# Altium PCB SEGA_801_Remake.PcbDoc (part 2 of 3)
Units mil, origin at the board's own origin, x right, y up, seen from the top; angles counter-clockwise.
Board outline 5905.51 x 7590.41 mil, 2 copper layers (Top Layer, Bottom Layer), stack 61.811 mil thick; 192 components, 203 nets, 858 pads, 614 vias.
Unrouted connection lines stored in the file: 107.
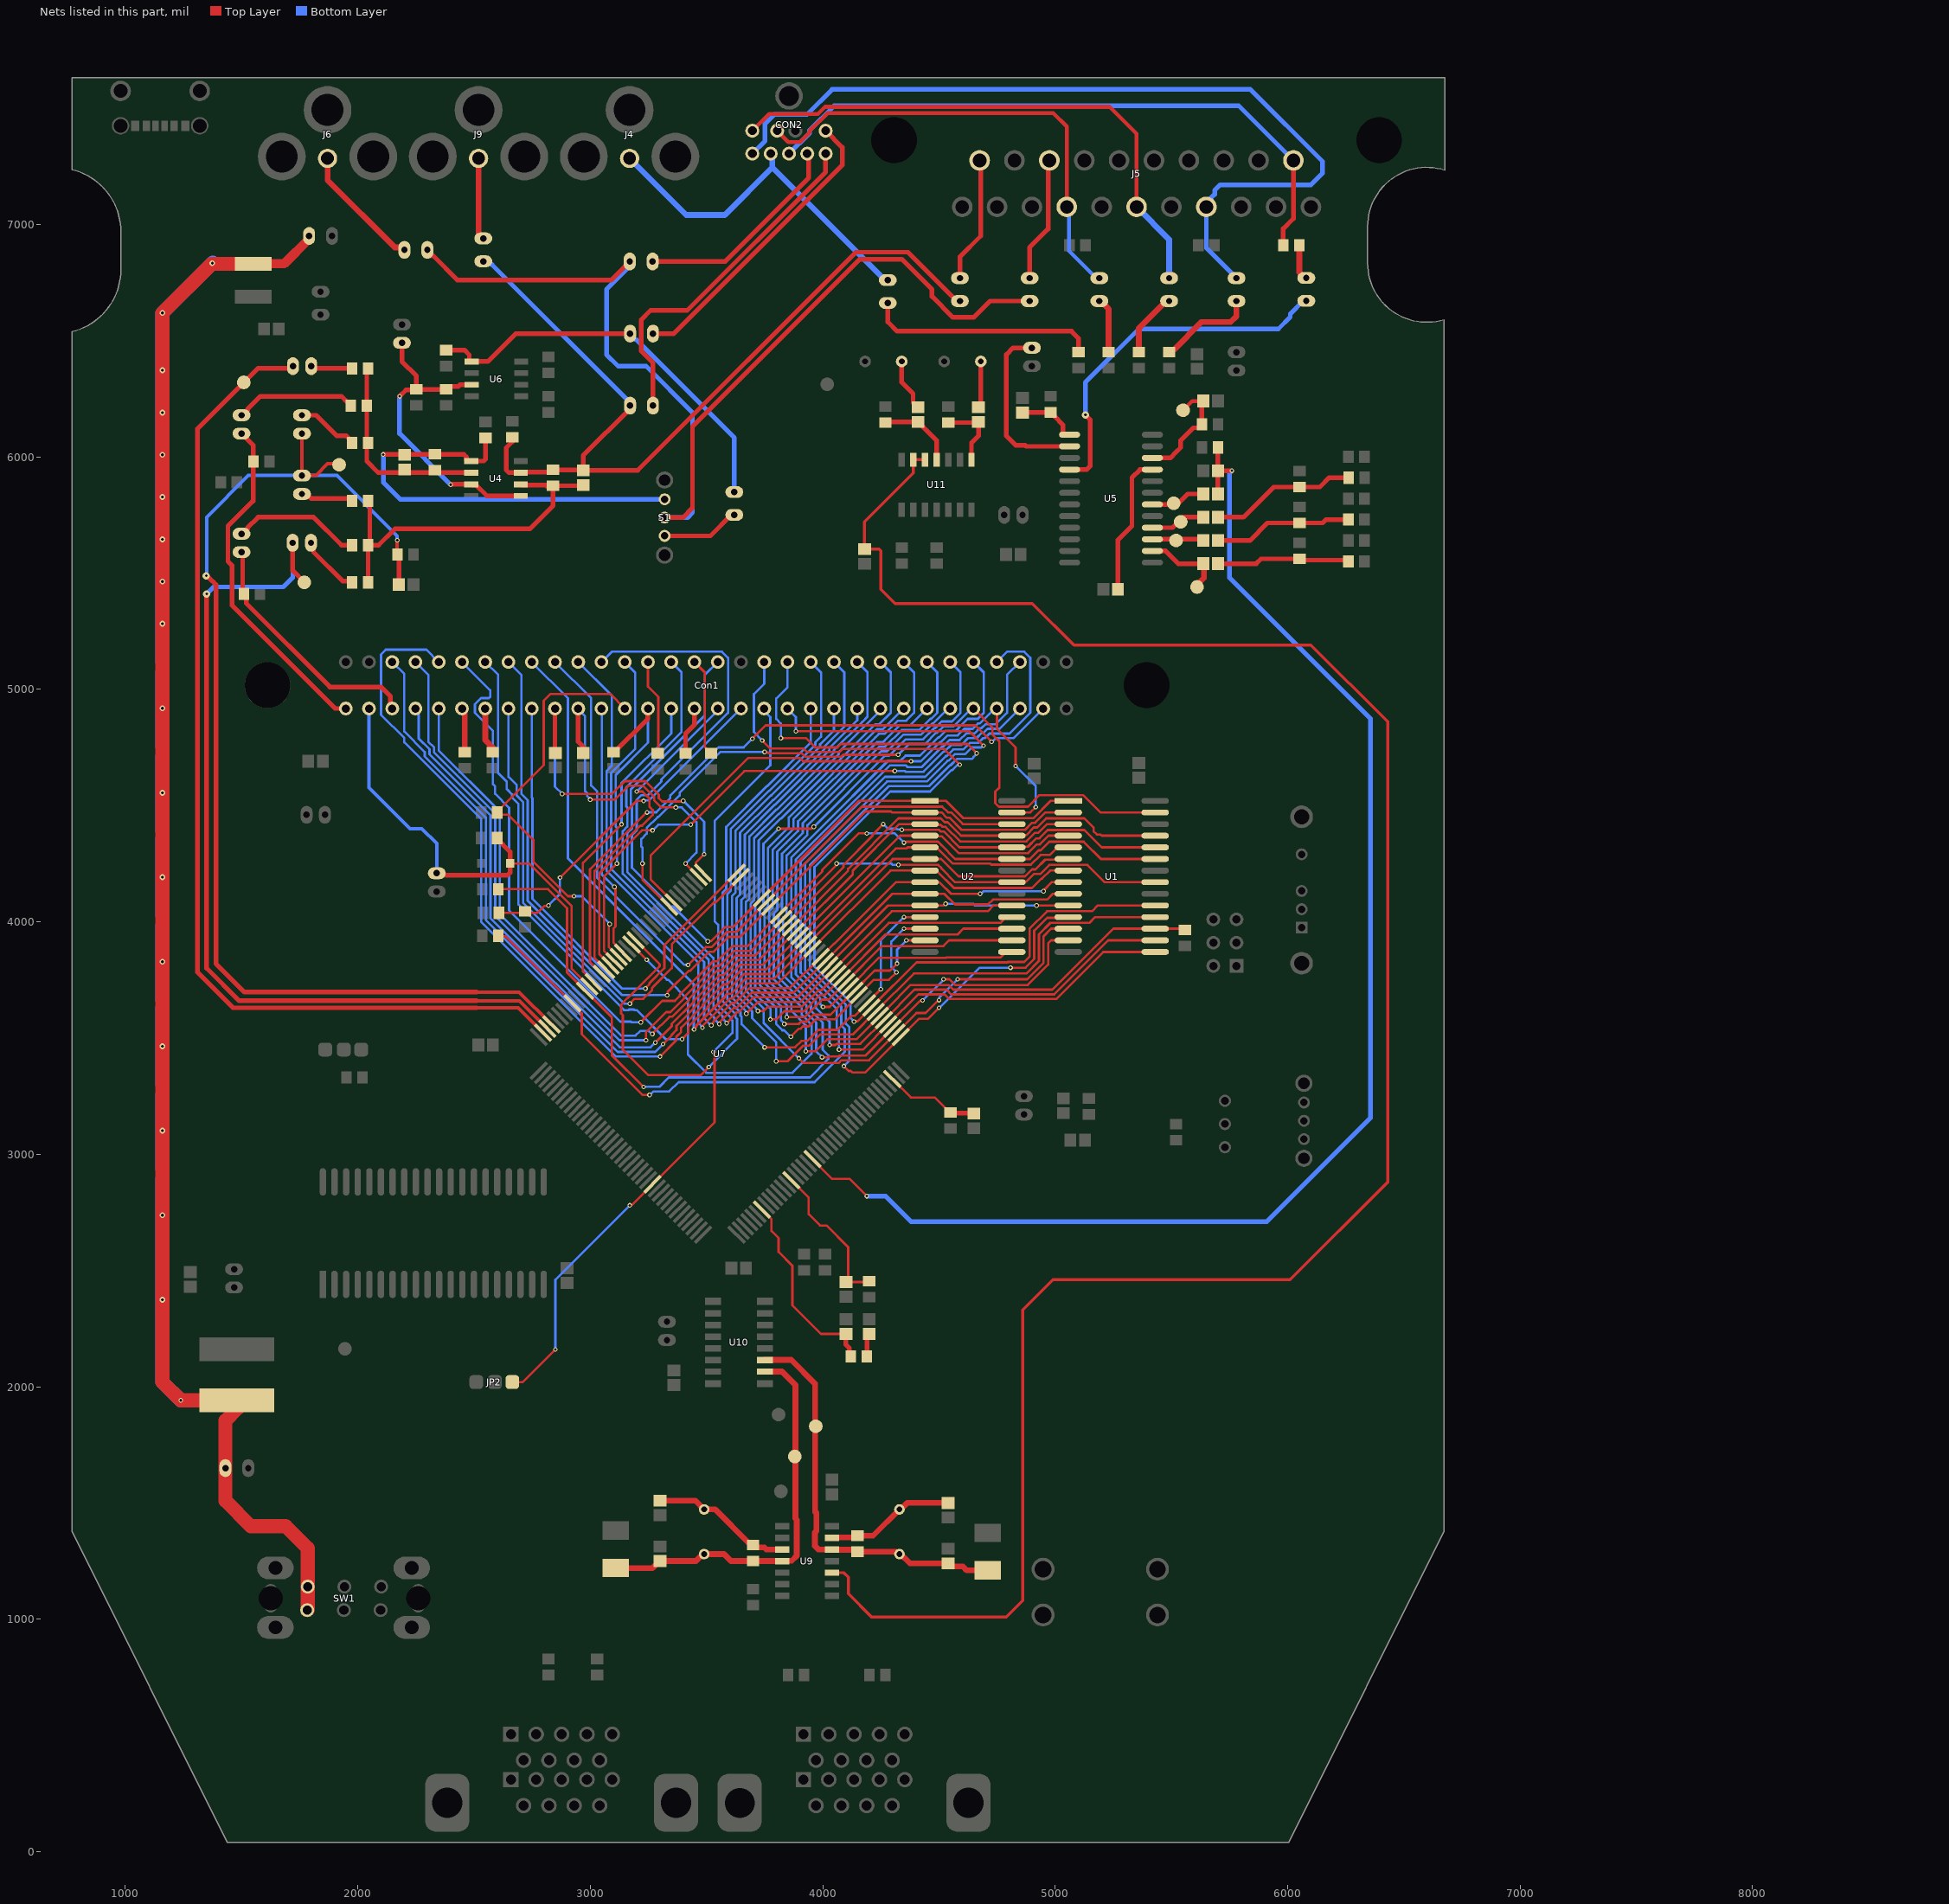
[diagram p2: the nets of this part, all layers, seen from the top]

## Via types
v1: diameter 25, hole 12, Top Layer to Bottom Layer, tented both sides, 269 vias
v2: diameter 19.68, hole 11.81, Top Layer to Bottom Layer, tented both sides, 183 vias
v3: diameter 31.5, hole 11.81, Top Layer to Bottom Layer, tented both sides, 82 vias
v4: diameter 23.62, hole 15.75, Top Layer to Bottom Layer, tented both sides, 36 vias
v5: diameter 35.43, hole 11.81, Top Layer to Bottom Layer, tented both sides, 35 vias
v6: diameter 39, hole 30, Top Layer to Bottom Layer, tented both sides, 7 vias
v7: diameter 19.68, hole 11.81, Top Layer to Bottom Layer, 2 vias

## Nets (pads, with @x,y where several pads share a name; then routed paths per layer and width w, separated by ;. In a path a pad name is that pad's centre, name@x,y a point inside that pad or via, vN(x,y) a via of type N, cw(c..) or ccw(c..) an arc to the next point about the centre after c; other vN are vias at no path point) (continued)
NetC4_1: C4.1 Con1.1 R2.2 | length 1487.6
  Top Layer w20: C4.1@1500,6100 1504.36,6100 1518.76,6085.6 1518.76,6081.24 1550,6050 1550,5980 1550,5810 1441.61,5701.61 1441.61,5550 1460,5531.61 1460,5360 1902.78,4917.22 Con1.1@1948.42,4917.22
NetC4_2: C4.2 R7.1 | length 525.1
  Top Layer w20: C4.2@1500,6178.74 1504.36,6178.74 1525.71,6200.09 1525.71,6204.45 1581.26,6260 1930,6260 1953.43,6236.57 1957.36,6236.57 1970,6223.94 R7.1@1970,6220
NetC5_1: C5.1 TP5.1 U7.159 | length 4455.8
  Top Layer w15: 2510,3630 2689.44,3630 U7.159@2797.17,3522.27
  Top Layer w20: C5.1@1726.22,6380 1570,6380 1310,6120 1310,3783.43 1463.43,3630 2510,3630
NetC5_2: C5.2 R8.1 | length 175.6
  Top Layer w20: C5.2@1799.95,6380 R8.1@1975.55,6380
NetC6_1: C6.1 C7.1 C66.1 R95.2 TP6.1 U7.157 | length 5074.3
  Top Layer w15: C6.1@1760,6100 1760,6060.63 C7.1@1760,5918.74 1762.15,5920.89 1820.89,5920.89 1870,5970 TP6.1@1920,5970 ; v2(2170,5641.43) 2170,5581.1 R95.2@2177.01,5574.09 ; 2510,3697.5 2694.35,3697.5 U7.157@2833.37,3558.47
  Top Layer w20: v3(1348.23,5488.23) 1351.34,5488.23 1375.43,5464.14 1375.86,5464.14 1390,5450 1390,3820 1512.5,3697.5 2510,3697.5 ; C66.1@2165.2,5450 2177.01,5461.81 R95.2@2177.01,5574.09
  Bottom Layer w15: v3(1348.23,5488.23) 1350,5490 1350,5740 1530,5920 1760,5920 1910,5920 2170,5660 v2(2170,5641.43)
NetC6_2: C6.2 R9.1 | length 260.2
  Top Layer w20: C6.2@1760,6178.74 1821.26,6178.74 1910,6090 1951.66,6090 R9.1@1974.16,6067.5
NetC7_2: C7.2 R10.1 | length 209
  Top Layer w20: C7.2@1760,5840 1780.1,5840 1800.1,5820 R10.1@1960.75,5820
NetC8_1: C8.1 TP8.1 U7.158 | length 3922.8
  Top Layer w15: 2510,3660 2695.64,3660 U7.158@2815.27,3540.37
  Top Layer w20: v3(1350,5410) 1350,3800 1490,3660 2510,3660 ; C8.1@1720,5630 1720,5510 TP8.1@1770,5460
  Bottom Layer w20: v3(1350,5410) 1380,5440 1680,5440 1720.63,5480.63 C8.1@1720.63,5630
NetC8_2: C8.2 R11.1 | length 264.1
  Top Layer w20: C8.2@1798.74,5630 1798.74,5608.77 1810.08,5597.43 1810.08,5589.92 1934.63,5465.37 1970.18,5465.37 R11.1@1975.55,5460
NetC9_1: C9.1 Con1.3 R1.1 | length 1070.7
  Top Layer w20: C9.1@1505,5590 1505,5405 1509.24,5405 1520.82,5393.43 1520.82,5369.18 1880,5010 2100,5010 2140.95,4969.05 2140.95,4924.69 Con1.3@2148.42,4917.22
NetC9_2: C9.2 R12.1 | length 557.3
  Top Layer w20: C9.2@1500,5668.74 1504.36,5668.74 1525.71,5690.09 1525.71,5694.45 1571.26,5740 1810,5740 1930,5620 R12.1@1975.55,5620
NetC11_1: C11.1 TP12.1 U5.2 | length 355.3
  Top Layer w20: U5.2@5418.15,5595 5475,5595 5530,5540 C11.1@5637.01,5540
  Top Layer w25: TP12.1@5610,5440 5610,5449.22 5640,5479.22 5640,5537.01 C11.1@5637.01,5540
NetC11_2: C11.2 R3.1 R19.1 | length 574.4
  Top Layer w20: C11.2@5700,5540 5864.51,5540 5885.61,5561.1 R3.1@6051.1,5561.1 6056.65,5555.55 6255.55,5555.55 R19.1@6261.1,5550
NetC12_1: C12.1 TP13.1 U5.3 | length 220.9
  Top Layer w20: U5.3@5418.15,5645 5530,5645 5632.01,5645 C12.1@5637.01,5640
NetC12_2: C12.2 R4.1 R18.1 | length 598.4
  Top Layer w20: C12.2@5700,5640 5837.28,5640 5912.83,5715.55 6150.85,5715.55 6165.3,5730 R18.1@6261.1,5730
NetC13_1: C13.1 TP14.1 U5.4 | length 237.5
  Top Layer w20: U5.4@5418.15,5695 5505,5695 5550,5740 C13.1@5637.01,5740
NetC13_2: C13.2 R5.1 R17.1 | length 632.6
  Top Layer w20: C13.2@5700,5740 5810.06,5740 5940.06,5870 6138.62,5870 6178.62,5910 R17.1@6262.21,5910
NetC14_1: C14.1 R13.2 R16.1 U4.3 U4.5 U6.3 | length 1350.8
  Top Layer w20: v2(2180,6260) 2207.22,6287.22 2249.31,6287.22 R16.1@2252.08,6290 ; C14.1@2190,6490 2190,6410 2252.08,6347.92 R16.1@2252.08,6290 ; v2(2400,5880) 2401.72,5881.72 U4.3@2488.26,5881.72 2491.06,5878.92 2508.28,5878.92 2555.49,5831.72 U4.5@2701.81,5831.72 ; U6.3@2490,6310 2440,6310 2432.64,6302.64 2392.64,6302.64 R13.2@2380,6290 R16.1@2252.08,6290
  Bottom Layer w20: v2(2180,6260) 2180,6100 v2(2400,5880)
NetC15_1: C15.1 R15.1 TP15.1 U5.10 | length 497.2
  Top Layer w17: TP15.1@5550,6200 5590,6240 C15.1@5637.01,6240
  Top Layer w20: U5.10@5418.15,5995 5495,5995 5519.84,6019.84 5519.84,6020.01 5540,6040.17 5540,6070 5594.91,6124.91 5616.96,6124.91 5631.1,6139.05 R15.1@5631.1,6140 5631.1,6234.09 C15.1@5637.01,6240
NetC16_1: C16.1 U5.9 | length 607.5
  Top Layer w20: C16.1@5270,5430 5270,5642.11 5330,5702.11 5330,5910 5365,5945 U5.9@5418.15,5945
NetC19_1: C19.1 R23.2 R24.1 S1.3 U4.1 | length 1914.4
  Top Layer w20: v2(2110,6010) 2456.53,6010 2468.24,5998.28 2468.24,5984.51 2471.04,5981.72 2541.72,5981.72 2550,5990 R24.1@2550,6081.1
  Bottom Layer w20: v2(2110,6010) 2110,5890 2182.68,5817.32 S1.3@3320,5817.32
NetC19_2: C19.2 R7.2 R8.2 R9.2 R23.1 U4.2 | length 858.7
  Top Layer w20: R8.2@2038.9,6370 R7.2@2038.9,6220 2038.9,6090 2038.9,5981.1 2088.28,5931.72 U4.2@2488.26,5931.72
NetC20_1: C20.1 C68.1 C70.1 C72.1 R20.2 R25.1 U4.7 | length 3829.3
  Top Layer w20: R25.1@2665.04,6064.89 2638.32,6038.17 2638.32,5943.43 2650.04,5931.72 U4.7@2701.81,5931.72 2704.6,5934.51 2833.18,5934.51 R20.2@2840,5941.33 ; R20.2@2840,5944.45 2841.48,5942.97 2965.87,5942.97 C20.1@2970,5938.84 ; C70.1@3171.57,6220 3171.57,6207.2 2970,6005.63 C20.1@2970,5941.5 3203.91,5941.5 4142.41,6880 4367.2,6880 4577.2,6670 C72.1@4590,6670
  Bottom Layer w20: C68.1@2540,6840.79 2561.23,6840.79 2575.15,6826.87 2577.5,6826.87 3171.57,6232.8 C70.1@3171.57,6220
NetC20_2: C20.2 R10.2 R11.2 R12.2 R20.1 U4.6 | length 1584.6
  Top Layer w20: R11.2@2044.45,5460 R12.2@2044.45,5620 ; R10.2@2044.45,5810 2051.97,5802.47 2051.97,5627.53 R12.2@2044.45,5620 ; U4.6@2701.81,5881.72 2704.6,5878.92 2808.38,5878.92 2815.04,5872.27 2818.15,5875.39 R20.1@2840,5875.39 ; C20.2@2970,5866.69 2961.31,5875.39 R20.1@2840,5875.39 ; R12.2@2044.45,5620 2090,5620 2160,5690 2740,5690 2840,5790 R20.1@2840,5875.39
NetC21_1: C21.1 R29.1 U5.13 | length 268
  Top Layer w20: C21.1@4860,6190 4860.55,6190.55 4979.45,6190.55 R29.1@4980,6191.1 4983.94,6191.1 4996.57,6178.47 4996.57,6174.53 5033.31,6137.8 5033.31,6097.58 5035.89,6095 U5.13@5061.85,6095
NetC22_1: C22.1 U5.16 | length 1566
  Top Layer w20: U5.16@5061.85,5945 5061.96,5945.11 5135.36,5945.11 5150,5959.76 5150,6160 v3(5130,6180)
  Bottom Layer w20: v3(5130,6180) 5130,6320 5360,6550 5960,6550 6011.1,6601.1 6011.1,6614.68 6067.2,6670.79 C22.1@6080,6670.79
NetC22_2: C22.2 R30.1 | length 156.6
  Top Layer w25: R30.1@6050,6910 6050,6793.5 6074.29,6769.21 C22.2@6080,6769.21
NetC25_1: C25.1 R37.2 | length 101.2
  Top Layer w10: C25.1@4190,2217.01 C25.1@4200,2227.01
  Top Layer w20: R37.2@4190,2130 C25.1@4190,2217.01
NetC26_1: C26.1 U5.14 | length 762.4
  Top Layer w20: C26.1@4900,6468.74 4818.74,6468.74 4790,6440 4790,6090 4830,6050 4870,6050 4875,6045 U5.14@5061.85,6045
NetC28_1: C28.1 C31.1 R28.2 U6.1 | length 1746.3
  Top Layer w20: R28.2@2380,6458.9 2459.39,6458.9 2480,6438.28 2480,6412.8 2482.8,6410 U6.1@2490,6410 2560,6410 2680,6530 C31.1@3171.57,6530
  Bottom Layer w20: C31.1@3171.57,6530 3171.57,6525.64 3192.92,6504.29 3197.28,6504.29 3620,6081.57 C28.1@3620,5848.43
NetC28_2: C28.2 S1.1 | length 337.3
  Top Layer w20: S1.1@3320,5659.84 3517.05,5659.84 3607.2,5750 C28.2@3620,5750
NetC29_1: C29.1 R37.1 U7.47 | length 853.2
  Top Layer w10: U7.47@3738.47,2761.99 3780,2720.46 3780,2670 3810,2640 3810,2580 3870,2520 3870,2350 3992.99,2227.01 C29.1@4100,2227.01 ; R37.1@4115.01,2136.09 R37.1@4121.1,2130
  Top Layer w20: C29.1@4100,2227.01 4100,2180.73 4115.01,2165.72 R37.1@4115.01,2136.09
NetC31_2: C31.2 CON2.6 | length 1291.8
  Top Layer w20: C31.2@3270,6530 3360,6530 4084.08,7254.08 4084.08,7330.65 CON2.6@4012.48,7402.24
NetC32_1: C32.1 R31.2 | length 419.4
  Top Layer w25: R31.2@5490,6450 5500.14,6460.14 5510.14,6460.14 5630,6580 5755.36,6580 5780,6604.64 C32.1@5780,6670
NetC32_2: C32.2 CON2.7 J5.15 | length 3732
  Bottom Layer w20: CON2.7@3697.52,7303.82 3752.05,7358.35 3752.05,7432.05 3792.8,7472.8 3932.8,7472.8 4040,7580 5840,7580 6150,7270 6150,7220 6100,7170 5710,7170 5685.86,7145.86 5685.86,7129.22 5650,7093.36 J5.15@5650,7074.8 5650,6898.43 5761.24,6787.19 5761.24,6782.83 5775.64,6768.43 C32.2@5780,6768.43
NetC33_1: C33.1 R32.2 | length 239.9
  Top Layer w25: C33.1@5190,6670 5195.71,6670 5230,6635.71 R32.2@5230,6450
NetC33_2: C33.2 CON2.1 J5.7 | length 2063.4
  Top Layer w17: CON2.1@3803.82,7402.24 3852.32,7353.74 3902.65,7353.74 3943.8,7394.89 3943.8,7402.15 3988.94,7447.3 3990.65,7447.3 4021.7,7478.34 4991.66,7478.34 5050,7420 J5.7@5050,7074.8
  Bottom Layer w17: J5.7@5050,7074.8 5060,7064.8 5060,6885.63 5177.2,6768.43 C33.2@5190,6768.43
NetC34_1: C34.1 R35.2 | length 281.3
  Top Layer w25: R35.2@5360,6450 5360,6552.8 5477.2,6670 C34.1@5490,6670
NetC34_2: C34.2 CON2.3 J5.11 | length 2444.2
  Top Layer w17: CON2.3@3697.52,7402.24 3697.52,7402.88 3769.64,7475 3822.17,7475 3822.88,7474.3 3979.47,7474.3 4010.52,7505.34 5234.66,7505.34 5350,7390 J5.11@5350,7074.8
  Top Layer w25: C34.2@5490,6768.43 5490.4,6768.43 C34.2@5504.8,6782.83
  Bottom Layer w25: J5.11@5350,7074.8 5490,6934.8 C34.2@5490,6768.43
NetC35_1: C35.1 R33.2 | length 990.6
  Top Layer w20: C35.1@4280,6661.57 4280,6580 4320,6540 5070,6540 5100,6510 R33.2@5100,6450
NetC35_2: C35.2 CON2.4 J4.1 | length 1559.1
  Bottom Layer w25: J4.1@3169.29,7283.46 3412.76,7040 3578.71,7040 3782.96,7244.25 ; CON2.4@3776.26,7303.82 3782.96,7297.12 3782.96,7244.25 ; C35.2@4280,6760 4267.2,6760 3782.96,7244.25
NetC36_1: C36.1 R39.1 U7.54 | length 666.4
  Top Layer w10: U7.54@3865.18,2888.7 3940,2813.88 3940,2742.08 3988.89,2693.19 4016.81,2693.19 4110,2600 4110,2460 C36.1@4100,2450 4195.55,2450 R39.1@4200,2454.45 R39.1@4196.06,2454.45
NetC37_2: C37.2 R52.1 U7.78 | length 413.7
  Top Layer w10: U7.78@4299.63,3323.15 4378.67,3244.11 4481.2,3244.11 4546.06,3179.25 R52.1@4550,3179.25 R52.1@4554.45,3174.8
  Top Layer w20: R52.1@4554.45,3174.8 4556.67,3177.03 4647.78,3177.03 C37.2@4650,3174.8
NetC39_2: C39.2 Con1.11 U7.122 | length 1448.6
  Top Layer w10: v2(3000,4525.16) 3105.16,4525.16 3164.84,4584.84 3228.31,4584.84 3274.84,4538.31 3274.84,4523.26 3306.3,4491.8 v2(3368.2,4491.8) ; v2(3410,4250) 3410,4249.49 3466.94,4192.55 U7.122@3466.94,4192.04
  Top Layer w20: Con1.11@2948.42,4917.22 2948.42,4774.57 2970,4752.99 C39.2@2970,4725.94
  Bottom Layer w10: Con1.11@2948.42,4917.22 2948.42,4913.36 2977.98,4883.8 2977.98,4562.02 2986.32,4553.68 2986.32,4541.46 3000,4527.78 v2(3000,4525.16) ; v2(3368.2,4491.8) 3393.33,4491.8 3457.41,4427.72 3457.41,4297.41 v2(3410,4250)
NetC40_2: C40.2 Con1.10 U7.121 | length 1537.3
  Top Layer w10: v2(2879.05,4550) 3093.81,4550 3148.66,4604.84 3236.59,4604.84 3294.84,4546.59 3294.84,4531.54 3309.39,4516.99 3394.37,4516.99 3397.38,4520 v2(3400,4520) ; U7.121@3485.05,4210.14 3454.99,4240.19 3454.99,4243.73 3453.5,4245.22 3453.5,4253.5 v2(3490,4290)
  Top Layer w20: Con1.10@2848.42,4917.22 2848.42,4727.52 C40.2@2850,4725.94
  Bottom Layer w10: Con1.10@2848.42,4917.22 2848.42,4580.63 v2(2879.05,4550) ; v2(3400,4520) 3490,4430 v2(3490,4290)
NetC49_2: C49.2 R61.2 U9.3 Y1.2 | length 612.4
  Top Layer w25: C49.2@3300,1510 3452.13,1510 Y1.2@3490,1472.13 3537.87,1472.13 3680.96,1329.04 3689.86,1329.04 R61.2@3700,1318.9 3710.14,1308.76 3748.66,1308.76 3757.42,1300 U9.3@3825.43,1300
NetC50_2: C50.2 R62.2 U9.13 Y2.2 | length 562.1
  Top Layer w25: U9.13@4040,1350 4041.28,1351.28 4142.38,1351.28 R62.2@4150,1358.9 4216.77,1358.9 Y2.2@4330,1472.13 4335.54,1472.13 4363.41,1500 C50.2@4540,1500
NetC53_1: C53.1 Con1.2 D1.1 R70.1 U7.148 | length 2072.1
  Top Layer w10: D1.1@2655.63,4250.63 2735.95,4250.63 2920,4066.58 2920,3797.68 U7.148@2996.29,3721.39
  Top Layer w20: C53.1@2340,4208.74 2345.97,4202.77 2377.33,4202.77 2380.1,4200 2643.91,4200 2655.63,4211.72 D1.1@2655.63,4250.63 2655.63,4300.43 2600,4356.06 R70.1@2600,4360
  Bottom Layer w15: Con1.2@2048.42,4917.22 2048.42,4576.32 2224.74,4400 2275.97,4400 2340,4335.97 C53.1@2340,4208.74
NetC55_1: C55.1 C81.1 L1.1 L2.1 SW1.1 SW1.2 | length 11569.3
  Top Layer w39: v1@1371.49,6830 v1@1381.81,6830 ; L2.1@1550,6830 1683.58,6830 1790.79,6937.2 C81.1@1790.79,6950
  Top Layer w60: v1@1371.49,6830 v1(1160,6618.51) v1(1160,6190.12) v1(1160,5463.28) v1(1160,3101.05) 1160,2020 v7(1238.82,1941.18) L1.1@1480,1941.18 ; v1@1381.81,6830 L2.1@1550,6830 ; L1.1@1484,1907.95 1430.79,1854.74 C55.1@1430.79,1650 1430.79,1509.21 1540,1400 1690,1400 1784.94,1305.06 SW1.2@1784.94,1140 SW1.1@1784.94,1041.27
  Bottom Layer w60: 1160,2893.42 v1(1160,2737.63) v1(1160,2374.21) 1160,2020 v7(1238.82,1941.18) ; 1160,2936.84 v1(1160,3101.05) 1160,3256.84 ; 1160,3300.26 v1(1160,3464.47) 1160,3630.26 ; 1160,3663.68 v1(1160,3827.89) 1160,3983.68 ; 1160,4027.1 v1(1160,4191.31) 1160,4357.1 ; 1160,4390.52 v1(1160,4554.73) 1160,4710.52 ; 1160,4753.94 v1(1160,4918.15) 1160,5073.94 ; 1160,5117.36 v1(1160,5281.57) 1160,5447.36 ; v1@1160,5460 v1(1160,5463.28) v1(1160,5644.99) v1(1160,5826.7) v1(1160,6008.41) v1(1160,6190.12) v1(1160,6371.83) v1(1160,6618.51) v1@1376.28,6834.78
  other v1: 1374.26,6832.86
NetC60_1: C60.1 R61.1 TP1.1 U9.4 U10.2 VC1.2 Y1.1 | length 1731.7
  Top Layer w20: VC1.2@3110,1220 VC1.2@3120,1210
  Top Layer w25: VC1.2@3110,1220 3268.03,1220 3298.03,1250 3454.46,1250 3484.46,1280 3575.73,1280 3605.73,1250 R61.1@3700,1250 U9.4@3825.43,1250 3826.71,1251.28 3866.97,1251.28 3888.44,1272.76 3888.44,1427.24 3882.34,1433.34 3882.34,1719.43 3882.5,1719.59 3882.5,2007.5 3825,2065 U10.2@3751.22,2065
NetC65_1: C65.1 R62.1 TP2.1 U9.12 U10.3 VC2.2 Y2.1 | length 1728.9
  Top Layer w25: U10.3@3751.22,2115 3865,2115 3967.03,2012.97 3967.03,1462.46 3973.13,1456.36 3973.13,1379.43 3966.44,1372.75 3966.44,1314.64 3981.09,1300 U9.12@4040,1300 4041.28,1298.72 4141.28,1298.72 R62.1@4150,1290 Y2.1@4314.46,1290 ; Y2.1@4330,1280 4335.19,1280 4375.19,1240 C65.1@4540,1240 4553.09,1226.91 4603.09,1226.91 4620,1210 VC2.2@4710,1210
NetC67_1: C67.1 C69.1 C71.1 S1.2 | length 4836.8
  Top Layer w20: C67.1@2288.92,6900.29 C67.1@2299.21,6890 2299.21,6885.64 2320.56,6864.29 2324.92,6864.29 2429.21,6760 3090,6760 3151.24,6821.24 3155.6,6821.24 3170,6835.64 C69.1@3170,6840 ; S1.2@3320,5738.58 3398.58,5738.58 3440,5780 3440,6130 4160,6850 4340,6850 4470,6720 4470,6690 4560,6600 4650,6600 4720,6670 C71.1@4890,6670
  Bottom Layer w20: C69.1@3170,6840 3170,6820 3070,6720 3070,6440 3120,6390 3240,6390 3440,6190 3440,5760 3418.58,5738.58 S1.2@3320,5738.58
NetC67_2: C67.2 J6.1 | length 548.5
  Top Layer w25: J6.1@1870.08,7283.46 1870.08,7189.92 2159.38,6900.62 2190.17,6900.62 C67.2@2200.79,6890
NetC68_2: C68.2 J9.1 | length 356
  Top Layer w25: J9.1@2519.68,7283.46 2520,7283.15 2520,6953.5 2534.29,6939.21 C68.2@2540,6939.21
NetC69_2: C69.2 CON2.8 | length 927.1
  Top Layer w20: C69.2@3268.43,6840 3580,6840 3940,7200 3940,7297.56 CON2.8@3933.74,7303.82
NetC70_2: C70.2 CON2.9 | length 1525.1
  Top Layer w20: C70.2@3270,6220 3270,6404.35 3220,6454.35 3220,6590 3260,6630 3417.57,6630 4012.48,7224.91 CON2.9@4012.48,7303.82
NetC71_2: C71.2 J5.6 | length 541.6
  Top Layer w20: C71.2@4890,6768.43 4890,6900 4970,6980 4970,7269.8 J5.6@4975,7274.8
NetC72_2: C72.2 J5.2 | length 545.7
  Top Layer w20: C72.2@4590,6768.42 4590,6860 4680,6950 4680,7269.8 J5.2@4675,7274.8
NetC73_1: C73.1 C74.1 R6.1 U7.59 | length 5995.8
  Top Layer w10: U7.59@3955.69,2979.21 4041.21,2893.7 4116.3,2893.7 v2(4190,2820)
  Top Layer w20: C73.1@5700,5840 C74.1@5700,5940 ; R6.1@5700,6040 C74.1@5700,5940 ; v2(5760,5940) C74.1@5700,5940
  Bottom Layer w20: v2(4190,2820) 4270,2820 4380,2710 5910,2710 6334.25,3134.25 6334.81,3134.25 6355.75,3155.19 6355.75,4874.25 5750,5480 5750,5930 v2(5760,5940)
NetC73_2: C73.2 TP11.1 U5.6 | length 237.5
  Top Layer w20: U5.6@5418.15,5795 5525,5795 5570,5840 C73.2@5637.01,5840
NetC75_1: C75.1 R75.1 U11.11 | length 338.2
  Top Layer w20: R75.1@4270,6147.05 4272.95,6150 C75.1@4410,6150 4411.97,6150 4431.06,6130.91 4431.06,6128.94 4490,6070 U11.11@4490,5987.28
NetC75_2: C75.2 L3.1 | length 227.2
  Top Layer w20: L3.1@4340,6410 4340,6320 4388.94,6271.06 4388.94,6232.08 4408.03,6212.99 C75.2@4410,6212.99
NetC76_1: C76.1 R76.1 U11.8 | length 300.5
  Top Layer w20: R76.1@4540,6147.05 4667.05,6147.05 4670,6144.09 4670,6090 4640,6060 U11.8@4640,5987.28
NetC76_2: C76.2 L4.1 | length 201.2
  Top Layer w20: C76.2@4670,6212.99 4680,6222.99 L4.1@4680,6410
NetC80_2: C80.2 U9.10 U11.12 U11.13 | length 9172.4
  Top Layer w13: U9.10@4040,1200 4090,1200 4110,1180 4110,1110 4210,1010 4790,1010 4860,1080 4860,2330 4990,2460 6010,2460 6430,2880 6430,4860 6100,5190 5081.01,5190 4902.01,5369 4311,5369 4250,5430 4250,5595.38 4242.38,5602.99 C80.2@4180,5602.99 4180,5720 4390,5930 U11.13@4390,5987.28 U11.12@4440,5987.28
NetCon1_4: Con1.4 U1.25 U2.25 U7.107 | length 4597.7
  Top Layer w10: v2(3280,3480) 3350.77,3550.77 3350.77,3560.78 3444.84,3654.86 3444.84,3659.99 3555.01,3770.16 3571.58,3770.16 3636.26,3834.84 3725.21,3834.84 U7.107@3865.18,3974.82 4109.21,4218.85 4109.21,4227.79 4326.02,4444.6 4507.9,4444.6 4524.41,4428.08 4536.77,4428.08 4594.85,4370 U2.25@4813.62,4370 4816.53,4372.91 4876.06,4372.91 4908.55,4405.4 4921.97,4405.4 4961.17,4444.6 5125.4,4444.6 5165.16,4404.84 5165.16,4389.71 5179.71,4375.16 5194.84,4375.16 5200,4370 U1.25@5380,4370
  Bottom Layer w10: Con1.4@2248.42,4917.22 2248.42,4903.94 2262.09,4890.28 2262.09,4787.91 2308.42,4741.58 2308.42,4719.87 2571.36,4456.94 2571.36,4015.51 3126.86,3460 3260,3460 v2(3280,3480)
NetCon1_5: Con1.5 U1.24 U2.24 U7.108 | length 4480.8
  Top Layer w10: v2(3267.43,3517.43) 3341.21,3591.21 3352.92,3591.21 3424.84,3663.14 3424.84,3668.27 3546.73,3790.16 3563.29,3790.16 3627.98,3854.84 3709.01,3854.84 U7.108@3847.08,3992.92 4089.21,4235.05 4089.21,4244.08 4214.84,4369.71 4214.84,4374.84 v2(4260,4420) ; v2(4340,4395.16) 4500.77,4395.16 4507.84,4388.08 4520.2,4388.08 4588.28,4320 U2.24@4813.62,4320 4816.53,4322.91 4882.63,4322.91 4918.47,4358.75 4931.89,4358.75 4967.74,4394.6 5125.4,4394.6 5200,4320 U1.24@5380,4320
  Bottom Layer w10: Con1.5@2348.42,4917.22 2348.42,4736.44 2611.36,4473.51 2611.36,4032.07 3133.43,3510 3195.13,3510 3215.13,3530 3252.25,3530 3264.81,3517.43 v2(3267.43,3517.43) ; v2(4260,4420) 4280,4400 4318.28,4400 4321.27,4397.01 4338.15,4397.01 v2(4340,4395.16)
NetCon1_6: Con1.6 R58.2 | length 172
  Top Layer w25: Con1.6@2448.42,4917.22 2448.42,4908 2460,4896.43 R58.2@2460,4750
NetCon1_7: Con1.7 R57.2 | length 182.6
  Top Layer w25: Con1.7@2548.42,4917.22 2548.42,4781.58 2565.93,4764.07 2565.93,4760.14 2576.06,4750 R57.2@2580,4750
NetCon1_8: Con1.8 U7.119 | length 2269.1
  Top Layer w10: v2(3170.65,3647.33) 3191.41,3668.09 3228.36,3668.09 3266.05,3705.79 3266.05,3715.26 3275.16,3724.36 3275.16,3725.14 3351.02,3801.01 3351.02,3902.71 3532.36,4084.05 3539.97,4084.05 U7.119@3647.96,4192.04
  Bottom Layer w10: Con1.8@2648.42,4917.22 2648.42,4622.88 2683.9,4587.41 2683.9,4542.39 2711.36,4514.93 2711.36,4082.07 3145.8,3647.63 3170.35,3647.63 v2(3170.65,3647.33)
NetCon1_9: Con1.9 U7.120 | length 2126.2
  Top Layer w10: v2(3237.57,3712.43) 3237.57,3715.05 3255.16,3732.65 3255.16,3736.87 3318.82,3800.54 3318.82,3899.1 U7.120@3629.86,4210.14
  Bottom Layer w10: Con1.9@2748.42,4917.22 2748.42,4534.43 2751.36,4531.5 2751.36,4098.64 3137.57,3712.43 v2(3237.57,3712.43)
NetCon1_12: Con1.12 U7.140 | length 1096.6
  Top Layer w10: v2(3103.78,4150) 3103.78,4147.38 3108.63,4142.54 3108.63,3979.71 3100,3971.08 3100,3910.85 3141.11,3869.74 U7.140@3141.11,3866.2
  Bottom Layer w10: Con1.12@3048.42,4917.22 3050,4915.64 3050,4203.78 v2(3103.78,4150)
NetCon1_13: Con1.13 R68.1 U7.141 | length 1847.9
  Top Layer w10: v2(2930,4110) 2904.87,4110 2755.86,4259.01 2755.86,4351.78 2647.64,4460 2610,4460 R68.1@2600,4470 2600,4473.94 2800,4673.94 2800,4950 2830,4980 3085.64,4980 Con1.13@3148.42,4917.22 ; v2(3083.78,3990) 3083.78,3987.38 3080,3983.59 3080,3891.11 U7.141@3123.01,3848.1
  Bottom Layer w10: v2(2930,4110) 2963.78,4110 v2(3083.78,3990)
NetCon1_14: Con1.14 R50.1 U7.142 | length 1451.7
  Top Layer w10: U7.142@3104.9,3830 3058.94,3875.96 3058.94,4194.1 v2(3114.84,4250)
  Top Layer w20: R50.1@3100,4728.9 3103.94,4728.9 3247.73,4872.69 3247.73,4916.52 Con1.14@3248.42,4917.22 ; R50.1@3101.1,4724.45 R50.1@3108.74,4732.09
  Bottom Layer w10: v2(3114.84,4250) 3114.84,4404.47 3110,4409.31 3110,4631.72 3248.42,4770.14 Con1.14@3248.42,4917.22
NetCon1_15: Con1.15 U7.147 | length 1354.2
  Top Layer w10: U7.147@3014.39,3739.49 2968.43,3785.45 2968.43,4252.8 v2(3134.84,4419.21)
  Bottom Layer w10: v2(3134.84,4419.21) 3134.84,4596.49 3348.42,4810.07 Con1.15@3348.42,4917.22
NetCon1_16: Con1.16 R51.2 | length 208.7
  Top Layer w20: R51.2@3410,4724.45 3410,4810 3448.42,4848.42 Con1.16@3448.42,4917.22
NetCon1_17: Con1.17 U7.144 | length 1440.1
  Top Layer w10: U7.144@3068.7,3793.8 3018.94,3843.56 3018.94,4217.52 3214.56,4413.13 3222.62,4413.13 3269.37,4459.89 3269.37,4480.47 3254.84,4494.99 3254.84,4530.03 3224.87,4560 v2(3200,4560)
  Bottom Layer w10: v2(3200,4560) 3548.42,4908.42 Con1.17@3548.42,4917.22
NetCon1_18: Con1.18 R40.2 R65.1 | length 1445.5
  Top Layer w10: R65.1@2607.52,4038.5 2769.61,4038.5 ; 2770,4038.9 2773.94,4038.9 2803.19,4068.15 2818.15,4068.15 v2(2820,4070) ; v2(2870,4190) 3200,4520 3229.74,4520 v2(3230,4519.74)
  Bottom Layer w10: v2(2820,4070) 2870,4120 v2(2870,4190) ; v2(3230,4519.74) 3231.85,4521.59 3252.79,4521.59 Con1.18@3648.42,4917.22
NetCon1_19: Con1.19 JP2.1 U7.28 | length 3465.7
  Top Layer w10: JP2.1@2665,2020 2710,2020 v2(2850,2160) ; v2(3170,2780) 3171.85,2781.85 3179.07,2781.85 3534.84,3137.62 3534.84,3432.54 3530,3437.38 v2(3530,3440)
  Bottom Layer w10: v2(2850,2160) 2850,2460 v2(3170,2780) ; v2(3530,3440) 3611.44,3521.44 3611.44,3573.78 3604.84,3580.38 3604.84,3586.65 3550,3641.5 3550,3987.18 3535.16,4002.03 3535.16,4433.44 3774.84,4673.13 3774.84,4880.67 3748.42,4907.08 Con1.19@3748.42,4917.22
NetCon1_20: Con1.20 R64.1 U7.152 | length 4709.9
  Top Layer w10: R64.1@2604.45,3940 2607.81,3936.64 2636.23,3936.64 U7.152@2923.88,3648.98 2923.88,3645.45 2963.34,3605.99 2963.34,3516.66 3224.86,3255.14 v2(3255.14,3255.14) ; v2(3884.84,4819.68) 4630,4819.68 v2(4692.27,4757.41)
  Bottom Layer w10: v2(3255.14,3255.14) 3257.77,3255.14 3272.62,3270 3340,3270 3380,3310 3965.13,3310 4094.84,3439.71 4094.84,3538.18 4080,3553.03 4080,3635.15 3924.84,3790.31 3924.84,4251.41 4276.86,4603.42 4448.57,4603.42 4537.84,4692.69 4541.43,4692.69 4570.02,4721.29 4613.45,4721.29 4641.98,4749.81 4682.06,4749.81 4689.65,4757.41 v2(4692.27,4757.41) ; Con1.20@3848.42,4917.22 3884.84,4880.8 v2(3884.84,4819.68)
NetCon1_21: Con1.21 U7.137 | length 2792.3
  Top Layer w10: U7.137@3195.41,3920.51 3298.82,3817.1 3298.82,3808.82 3162.17,3672.17 3160.36,3672.17 3145.8,3657.62 3145.8,3655.8 3132.92,3642.92 3132.92,3605.12 3140,3598.05 3140,3450 3250,3340 3475.16,3340 v2(3510,3374.84)
  Bottom Layer w10: v2(3510,3374.84) 3624.84,3489.69 3631.44,3496.29 3631.44,3582.07 3624.84,3588.67 3624.84,3603.43 3570,3658.27 3570,4126.84 3584.84,4141.68 3584.84,4408.27 3759.98,4583.41 3762.31,4583.41 3948.42,4769.52 Con1.21@3948.42,4917.22
NetCon1_22: Con1.22 U2.19 U7.97 | length 2826
  Top Layer w10: v2(3671.51,3605) 3671.51,3605.61 3720.74,3654.84 3902.85,3654.84 U7.97@4024,3775.99 ; U7.97@4046.2,3793.8 4297.81,4045.4 4710.8,4045.4 4735.4,4070 U2.19@4813.62,4070
  Bottom Layer w10: v2(3671.51,3605) 3669.65,3606.85 3669.65,3615.19 3668.02,3616.82 3610,3674.84 3610,4110.27 3624.84,4125.12 3624.84,4391.4 3776.86,4543.41 3778.88,4543.41 3988.42,4752.95 3988.42,4763.25 4048.42,4823.25 Con1.22@4048.42,4917.22
NetCon1_23: Con1.23 U2.18 U7.96 | length 2798.3
  Top Layer w10: v2(3721.41,3615.78) 3745.78,3615.78 3764.84,3634.84 3911.14,3634.84 3981.14,3704.84 3993.45,3704.84 U7.96@4064.31,3775.69 4283.77,3995.16 4763.98,3995.16 4788.82,4020 U2.18@4813.62,4020
  Bottom Layer w10: v2(3721.41,3615.78) 3721.41,3618.4 3714.72,3625.09 3714.72,3625.62 3712.3,3628.04 3712.3,3629.11 3650,3691.41 3650,4093.71 3664.84,4108.55 3664.84,4374.83 3793.42,4503.41 3795.45,4503.41 4028.42,4736.38 4028.42,4746.68 4148.42,4866.68 Con1.23@4148.42,4917.22
NetCon1_24: Con1.24 U2.17 U7.95 | length 2805
  Top Layer w10: v2(3775.16,3580) 3800.02,3580 3834.87,3614.84 3919.42,3614.84 3989.42,3684.84 4009.65,3684.84 U7.95@4082.41,3757.59 4082.79,3757.59 4270.35,3945.16 4580.27,3945.16 4605.12,3970 U2.17@4813.62,3970
  Bottom Layer w10: v2(3775.16,3580) 3775.16,3625.44 3704.84,3695.76 3690,3710.6 3690,4077.14 3704.84,4091.98 3704.84,4358.26 3809.99,4463.41 3812.02,4463.41 4068.42,4719.81 4068.42,4730.11 4248.42,4910.11 Con1.24@4248.42,4917.22
NetCon1_25: Con1.25 U2.16 U7.94 | length 2735.5
  Top Layer w10: v2(3845.16,3590) 3922.87,3590 3997.71,3664.84 4025.86,3664.84 U7.94@4100.51,3739.49 4100.51,3740.51 4255.16,3895.16 4518.66,3895.16 4543.5,3920 U2.16@4813.62,3920
  Bottom Layer w10: v2(3845.16,3590) 3845.16,3640.3 3750,3735.45 3750,4052.28 3764.84,4067.13 3764.84,4317.68 3825.47,4378.31 3854.07,4406.91 3854.07,4448.89 4233.3,4828.12 4258.15,4828.12 4347.25,4917.22 Con1.25@4348.42,4917.22
NetCon1_26: Con1.26 U7.138 | length 3041.3
  Top Layer w10: U7.138@3177.31,3902.41 v2(3243.15,3836.57)
  Bottom Layer w10: v2(3243.15,3836.57) 3329.71,3750.01 3335.13,3750.01 3419.84,3665.3 3419.84,3429.87 3499.71,3350 3870,3350 3952.28,3432.28 3952.28,3557.72 3910,3600 3910,3632.02 3790,3752.02 3790,4035.72 3804.84,4050.56 3804.84,4301.12 3842.03,4338.31 3894.07,4390.34 3894.07,4432.32 4234.85,4773.11 4259.71,4773.11 4274.72,4788.12 4331.44,4844.84 4376.05,4844.84 Con1.26@4448.42,4917.22
NetCon1_27: Con1.27 R66.1 U7.149 | length 4036.6
  Top Layer w10: R66.1@2600,4140 2818.3,4140 2900,4058.3 2900,3781.48 U7.149@2978.19,3703.29 3092.92,3588.56 3092.92,3425.69 v2(3229.31,3289.31)
  Bottom Layer w10: v2(3229.31,3289.31) 3230,3290 3297.49,3290 3337.49,3330 3945.13,3330 4024.84,3409.71 4024.84,3424.89 4000,3449.73 4000,3566.57 3950,3616.57 3950,3648.59 3830,3768.59 3830,4019.15 3844.84,4033.99 3844.84,4284.55 3934.07,4373.78 3934.07,4415.76 4251.42,4733.11 4276.27,4733.11 4348.01,4804.84 4423.72,4804.84 4471.56,4852.69 4475.15,4852.69 4539.68,4917.22 Con1.27@4548.42,4917.22
NetCon1_28: Con1.28 U1.27 U7.129 | length 3194.9
  Top Layer w10: v2(3224.53,4250.4) 3224.53,4181.03 U7.129@3340.23,4065.33 ; v2(3750,4730) 3751.85,4728.15 3763.57,4728.15 3766.87,4724.84 3909.1,4724.84 3923.94,4710 4080.11,4710 4088.07,4717.95 v2(4324.53,4717.95) ; Con1.28@4648.42,4917.22 4730,4835.64 4730,4806.1 4760,4776.1 4760,4577.15 4742.57,4559.72 4742.57,4509.81 4757.38,4495 4883.06,4495 4932.66,4544.6 5120.4,4544.6 5195,4470 U1.27@5380,4470
  Bottom Layer w10: v2(3224.53,4250.4) 3224.53,4319.06 3219.68,4323.9 3219.68,4355.78 3243.42,4379.52 3243.42,4403.42 3291.04,4451.04 3292.31,4451.04 3384.83,4543.56 3384.83,4555.08 3559.76,4730 v2(3750,4730) ; v2(4324.53,4717.95) 4371.42,4764.84 4440.28,4764.84 4488.13,4812.69 4491.72,4812.69 4520.32,4841.29 4563.75,4841.29 4639.68,4917.22 Con1.28@4648.42,4917.22
NetCon1_29: Con1.29 U2.27 U7.128 | length 2611.3
  Top Layer w10: U7.128@3358.33,4083.43 3260,4181.76 3260,4285.5 3679.35,4704.84 3900.81,4704.84 3915.66,4690 v2(4380,4690) ; Con1.29@4748.42,4917.22 4750,4915.64 4750,4830.04 4830,4750.04 v2(4830,4670) ; U2.27@4813.62,4470 4893.19,4470 v2(4916.6,4493.4)
  Bottom Layer w10: v2(4380,4690) 4422.01,4690 4504.7,4772.69 4508.29,4772.69 4536.88,4801.29 4580.32,4801.29 4608.84,4829.81 4644.69,4829.81 4667.57,4852.69 4675.15,4852.69 4739.68,4917.22 Con1.29@4748.42,4917.22 ; v2(4830,4670) 4916.6,4583.4 v2(4916.6,4493.4)
NetCon1_30: Con1.30 U7.143 | length 2522.5
  Top Layer w10: U7.143@3086.8,3811.9 3038.94,3859.76 3038.94,4209.23 3222.84,4393.13 v2(3268.27,4393.13) ; v2(3432.57,4417.43) 3663.4,4648.27 v2(4310,4648.27)
  Bottom Layer w10: v2(3268.27,4393.13) 3292.57,4417.43 v2(3432.57,4417.43) ; v2(4310,4648.27) 4354.04,4648.27 4357.15,4645.16 4433.74,4645.16 4521.27,4732.69 4524.86,4732.69 4553.45,4761.29 4596.89,4761.29 4625.41,4789.81 4661.26,4789.81 4684.14,4812.69 4691.72,4812.69 4708.77,4829.74 4760.94,4829.74 Con1.30@4848.42,4917.22
NetCon1_31: Con1.31 U7.145 | length 2772.3
  Top Layer w10: U7.145@3050.6,3775.69 2998.94,3827.35 2998.94,4225.8 3243.32,4470.18 v2(3244.53,4470.18) ; v2(3697.43,4787.43) 3754.53,4844.53 4656.44,4844.53 v2(4726.71,4774.26)
  Bottom Layer w10: v2(3244.53,4470.18) 3245.39,4471.04 3284.03,4471.04 3344.53,4531.54 3344.53,4543.06 3551.47,4750 3660,4750 v2(3697.43,4787.43) ; v2(4726.71,4774.26) 4729.33,4774.26 4744.81,4789.74 4820.94,4789.74 Con1.31@4948.42,4917.22
NetCon1_35: Con1.35 U2.15 U7.93 | length 3010.8
  Top Layer w10: v2(4001.23,3633.23) 4030.45,3633.23 U7.93@4118.61,3721.39 4242.38,3845.16 4530.29,3845.16 4532.23,3847.1 4765.92,3847.1 4788.82,3870 U2.15@4813.62,3870
  Bottom Layer w10: v2(4001.23,3633.23) 3990,3644.46 3990,3668.58 3884.84,3773.74 3884.84,4267.98 4289.97,4673.11 4357.49,4673.11 4365.44,4665.16 4399.71,4665.16 4425.45,4665.16 4512.99,4752.69 4516.57,4752.69 4545.17,4781.29 4588.6,4781.29 4617.12,4809.81 4652.98,4809.81 4675.86,4832.69 4683.44,4832.69 4700.48,4849.74 4743.92,4849.74 4792.95,4898.77 4792.95,5061.75 Con1.35@4848.42,5117.22
NetCon1_36: Con1.36 U1.15 U7.84 | length 4042.1
  Top Layer w10: v2(4070,3450) 4173.06,3450 U7.84@4281.53,3558.47 4410.79,3687.73 4524.86,3687.73 4544.86,3667.73 5004.3,3667.73 5206.57,3870 U1.15@5380,3870
  Bottom Layer w10: v2(4070,3450) 4070,3534.74 4060,3544.74 4060,3626.86 3904.84,3782.02 3904.84,4259.69 4268.57,4623.42 4440.29,4623.42 4529.55,4712.69 4533.14,4712.69 4561.74,4741.29 4605.17,4741.29 4633.69,4769.81 4669.54,4769.81 4689.51,4789.77 4697.09,4789.77 4717.05,4809.74 4803.92,4809.74 4892.95,4898.77 4892.95,5135.66 4866.87,5161.75 4792.95,5161.75 Con1.36@4748.42,5117.22
NetCon1_37: Con1.37 U1.16 U7.85 | length 3750.5
  Top Layer w10: v2(4030,3470) 4054.87,3470 4059.71,3474.84 4161.69,3474.84 U7.85@4263.43,3576.57 ; U7.85@4263.43,3576.57 4394.58,3707.73 4533.14,3707.73 4553.14,3687.73 4996.01,3687.73 5228.28,3920 U1.16@5380,3920
  Bottom Layer w10: v2(4030,3470) 4030,3569.33 3970,3629.33 3970,3656.87 3864.84,3762.03 3864.84,4276.26 3972.01,4383.43 4281.69,4693.11 4334.82,4693.11 4356.56,4714.84 4418.57,4714.84 4496.42,4792.69 4500,4792.69 4528.6,4821.29 4572.03,4821.29 4600.56,4849.81 4623.44,4872.69 4666.87,4872.69 4692.95,4898.77 4692.95,5072.69 Con1.37@4648.42,5117.22
NetCon1_38: Con1.38 U2.13 U7.92 | length 2932.8
  Top Layer w10: v2(3810,4400) 3950.83,4400 3959.1,4408.28 v2(3961.72,4408.28) ; v2(3834.84,3560) 3896.6,3560 3906.6,3570 3931.15,3570 3961.15,3600 4033.42,3600 U7.92@4136.71,3703.29 4223.42,3790 4290,3790 v2(4320,3820) ; v2(4360,3920) U2.13@4440,3920
  Bottom Layer w10: v2(3810,4400) 3809.3,4400 3744.84,4335.55 3744.84,4075.41 3730,4060.57 3730,3727.17 3744.84,3712.33 3820,3637.17 3820,3577.46 3834.84,3562.62 v2(3834.84,3560) ; v2(3961.72,4408.28) 4266.55,4713.11 4284.56,4713.11 4356.29,4784.84 4432,4784.84 4479.85,4832.69 4483.44,4832.69 4512.03,4861.29 4555.46,4861.29 4592.95,4898.77 4592.95,5072.69 Con1.38@4548.42,5117.22 ; v2(4320,3820) 4320,3880 v2(4360,3920)
NetCon1_39: Con1.39 U1.13 U7.83 | length 3432.7
  Top Layer w10: v2(3997.3,3417.3) 4024.44,3417.3 4027.14,3420 4068.32,3420 4072.29,3423.98 4183.24,3423.98 4418.69,3659.43 4428.15,3659.43 v2(4430,3661.29) ; v2(4520,3752.57) 4544.87,3752.57 4569.71,3727.73 4882.58,3727.73 4970,3815.15 4970,3907.68 4982.32,3920 U1.13@5006.38,3920
  Bottom Layer w10: v2(3997.3,3417.3) 3972.28,3442.33 3972.28,3566.01 3930,3608.28 3930,3640.31 3810,3760.31 3810,4027.43 3824.84,4042.27 3824.84,4292.83 3914.07,4382.06 3914.07,4424.04 4243.14,4753.11 4267.99,4753.11 4339.72,4824.84 4415.43,4824.84 4463.28,4872.69 4466.87,4872.69 4492.95,4898.77 4492.95,5072.69 Con1.39@4448.42,5117.22 ; v2(4430,3661.29) 4520,3751.29 v2(4520,3752.57)
NetCon1_40: Con1.40 R63.1 U1.17 U7.86 | length 3875.9
  Top Layer w10: v2(3927.43,3442.57) 3967.43,3442.57 4019.71,3494.84 4145.49,3494.84 U7.86@4245.32,3594.68 ; U7.86@4276.46,3625.81 4277.14,3626.5 4378.38,3727.73 4541.43,3727.73 4561.43,3707.73 4987.73,3707.73 5250,3970 U1.17@5430,3970 5552.49,3970 R63.1@5558.13,3964.36
  Bottom Layer w10: v2(3927.43,3442.57) 3927.43,3554.28 3865.16,3616.56 3865.16,3648.58 3770,3743.74 3770,4044 3784.84,4058.84 3784.84,4309.4 3833.75,4358.31 3874.07,4398.63 3874.07,4440.61 4226.57,4793.11 4241.59,4808.12 4266.44,4808.12 4323.16,4864.84 4359.02,4864.84 4392.95,4898.77 4392.95,5072.69 Con1.40@4348.42,5117.22
NetCon1_41: Con1.41 U2.12 U7.91 | length 2831.8
  Top Layer w10: v2(3862.88,3504.84) 3898.03,3540 3904.88,3540 3914.88,3550 3939.43,3550 3969.43,3580 4051.72,3580 4154.81,3683.1 U7.91@4154.81,3685.19 4219.63,3750 4285.13,3750 v2(4317.26,3782.13) ; v2(4350,3970) U2.12@4440,3970
  Bottom Layer w10: v2(3862.88,3504.84) 3834.52,3533.2 3826.51,3533.2 3800,3559.71 3800,3628.88 3724.84,3704.04 3710,3718.89 3710,4068.85 3724.84,4083.7 3724.84,4349.98 3818.28,4443.41 3820.3,4443.41 4225.02,4848.12 4242.3,4848.12 4292.95,4898.77 4292.95,5072.69 Con1.41@4248.42,5117.22 ; v2(4317.26,3782.13) 4295.16,3804.23 4295.16,3915.16 v2(4350,3970)
NetCon1_42: Con1.42 U1.12 U7.82 | length 3464.2
  Top Layer w10: v2(3897.43,3412.57) 3917.54,3392.46 4069.06,3392.46 4080.58,3403.98 4199.44,3403.98 4403.02,3607.56 4442.43,3607.56 4497.76,3662.89 v2(4500,3662.89) ; v2(4580,3752.57) 4879.14,3752.57 4950,3823.43 4950,3937.68 4982.32,3970 U1.12@5006.38,3970
  Bottom Layer w10: v2(3897.43,3412.57) 3746.25,3563.75 3746.25,3626.07 3670,3702.32 3670,4085.42 3684.84,4100.26 3684.84,4366.54 3801.71,4483.41 3803.73,4483.41 4048.42,4728.1 4048.42,4738.39 4168.42,4858.39 4192.95,4882.92 4192.95,5072.69 Con1.42@4148.42,5117.22 ; v2(4500,3662.89) 4501.85,3664.74 4501.85,3674.43 v2(4580,3752.57)
NetCon1_43: Con1.43 U1.18 U7.87 | length 3902.8
  Top Layer w10: v2(3800,3400) 3849.74,3400 3917.14,3467.41 3941.69,3467.41 3989.13,3514.84 4129.28,3514.84 U7.87@4227.22,3612.78 4391.86,3777.42 4875.7,3777.42 4930,3831.72 4930,3945.96 4979.44,3995.4 5147.88,3995.4 5172.48,4020 U1.18@5380,4020
  Bottom Layer w10: v2(3800,3400) 3800,3481.72 3696.56,3585.15 3696.56,3614.39 3692.3,3618.66 3692.3,3620.83 3630,3683.13 3630,4101.99 3644.84,4116.83 3644.84,4383.11 3785.14,4523.41 3787.17,4523.41 4008.42,4744.67 4008.42,4754.96 4092.95,4839.49 4092.95,5072.69 Con1.43@4048.42,5117.22
NetCon1_44: Con1.44 U2.11 U7.89 | length 2956.2
  Top Layer w10: v2(3750,3460) 3881.45,3460 3908.86,3487.41 3933.41,3487.41 3980.84,3534.84 4063.13,3534.84 4123.13,3594.84 4136.88,3594.84 U7.89@4191.02,3648.98 4191.02,3650 4250,3708.98 v2(4250,3710) ; v2(4350,4020) U2.11@4440,4020
  Bottom Layer w10: v2(3750,3460) 3651.44,3558.56 3651.44,3590.35 3646.27,3595.52 3646.27,3610.29 3590,3666.56 3590,4118.56 3604.84,4133.4 3604.84,4399.68 3768.57,4563.41 3770.6,4563.41 3968.42,4761.24 3968.42,4771.53 3992.95,4796.06 3992.95,5072.69 Con1.44@3948.42,5117.22 ; v2(4250,3710) 4250,3920 v2(4350,4020)
NetCon1_45: Con1.45 U1.11 U7.81 | length 4409.6
  Top Layer w10: v2(3820,4790) 3927.81,4790 3967.81,4750 4063.55,4750 4078.39,4764.84 4622.56,4764.84 v2(4662.43,4724.97) ; v2(4090.87,3379.13) 4111.85,3358.15 4120.85,3358.15 4127.14,3351.85 4183.52,3351.85 4413.73,3582.07 4452.07,3582.07 v2(4500,3630) ; v2(4807.93,3802.26) 4872.26,3802.26 4910,3840 4910,3961.5 4965.6,4017.09 5037.09,4017.09 U1.11@5040,4020
  Bottom Layer w10: v2(3820,4790) 3820,4852.19 3800,4872.19 3800,4960 3848.42,5008.42 Con1.45@3848.42,5117.22 ; v2(4090.87,3379.13) 4114.84,3403.11 4114.84,3546.47 4100,3561.31 4100,3643.43 3944.84,3798.59 3944.84,4243.13 4285.14,4583.42 4456.86,4583.42 4546.12,4672.69 4549.71,4672.69 4577.02,4700 4641.72,4700 4648.79,4707.07 4648.79,4708.7 4662.43,4722.35 v2(4662.43,4724.97) ; v2(4500,3630) 4502.24,3630 4674.5,3802.26 v2(4807.93,3802.26)
NetCon1_46: Con1.46 U1.19 U7.88 | length 4339.9
  Top Layer w10: v2(3740,4780) 3775.16,4744.84 3917.38,4744.84 3932.23,4730 4071.83,4730 4084.62,4742.79 4522.36,4742.79 v2(4590,4675.16) ; v2(4134.84,3570) 4136.7,3571.85 4150.09,3571.85 U7.88@4209.12,3630.88 4403.4,3825.16 4795.7,3825.16 4797.64,3827.1 4867.1,3827.1 4890,3850 4890,3969.78 4965.62,4045.4 5158.77,4045.4 5183.37,4070 U1.19@5380,4070
  Bottom Layer w10: v2(3740,4780) 3703.9,4816.1 3703.9,4979.1 3748.42,5023.62 Con1.46@3748.42,5117.22 ; v2(4134.84,3570) 4120,3584.84 4120,3651.72 3964.84,3806.87 3964.84,4234.84 4290,4560 4461.72,4560 4554.41,4652.69 4557.99,4652.69 4578.61,4673.3 4588.15,4673.3 v2(4590,4675.16)
NetCon1_48: Con1.48 U1.10 U2.10 U7.98 | length 3520
  Top Layer w10: v2(3586.6,3563.49) 3609.15,3586.04 3609.15,3589.46 3629.84,3610.16 3637.85,3610.16 3702.54,3674.84 3891.04,3674.84 U7.98@4028.1,3811.9 ; U7.98@4035.91,3824.09 4281.82,4070 4519,4070 4526.16,4077.16 v2(4528.79,4077.16) ; v2(4920,4070) U1.10@5006.38,4070
  Bottom Layer w10: Con1.48@3548.42,5117.22 3492.95,5061.75 3492.95,4888.08 3175.16,4570.29 3175.16,4504.29 3179.68,4499.77 3179.68,4400.63 3159.68,4380.63 3159.68,4214.08 3530,3843.77 3530,3633.21 3570.34,3592.87 3570.34,3582.37 3586.6,3566.11 v2(3586.6,3563.49) ; v2(4528.79,4077.16) 4647.84,4077.16 4655,4070 v2(4920,4070)
NetCon1_49: Con1.49 R59.2 | length 424.7
  Top Layer w10: Con1.49@3448.42,5117.22 3492.95,5072.69 3492.95,4751.5 3498.43,4746.02 3498.43,4742.09 3516.06,4724.45 R59.2@3520,4724.45
NetCon1_50: Con1.50 U1.9 U2.9 U7.99 | length 3581.7
  Top Layer w10: v2(3554.87,3560.04) 3556.72,3561.9 3556.72,3568.74 3618.13,3630.16 3629.57,3630.16 3694.25,3694.84 3874.84,3694.84 4300,4120 U2.9@4440,4120 4523.38,4120 4569.22,4074.17 4711.28,4074.17 4732.52,4095.4 4965.4,4095.4 4990,4120 U1.9@5006.38,4120
  Bottom Layer w10: Con1.50@3348.42,5117.22 3392.95,5072.69 3392.95,4816.37 3155.16,4578.57 3155.16,4496.01 3159.68,4491.48 3159.68,4408.92 3139.68,4388.92 3139.68,4205.8 3510,3835.49 3510,3610 3533.75,3586.25 3533.75,3581.16 v2(3554.87,3560.04)
NetCon1_51: Con1.51 R60.2 | length 396.9
  Top Layer w10: Con1.51@3248.42,5117.22 3248.42,5011.58 3292.95,4967.05 3292.95,4742.95 R60.2@3290,4740
NetCon1_52: Con1.52 U1.8 U2.8 U7.100 | length 3591.2
  Top Layer w10: v2(3520.7,3554.16) 3520.7,3556.79 3530.02,3566.11 3530.02,3570.33 3609.85,3650.16 3621.28,3650.16 3685.97,3714.84 3858.63,3714.84 U7.100@3991.9,3848.1 3991.9,3848.46 4048.59,3905.16 4050.29,3905.16 4315.13,4170 4501.67,4170 4551.67,4120 v2(4677.46,4120) ; v2(4949.84,4131.21) 4951.7,4133.06 4951.7,4136.84 4984.85,4170 U1.8@5006.38,4170
  Bottom Layer w10: Con1.52@3148.42,5117.22 3192.95,5072.69 3192.95,4742.95 3120,4670 3090,4640 3090,4227.2 3490,3827.2 3490,3584.87 v2(3520.7,3554.16) ; v2(4677.46,4120) 4680.08,4120 4691.29,4131.21 v2(4949.84,4131.21)
NetCon1_53: Con1.53 U1.1 U2.1 U7.114 | length 3934.8
  Top Layer w10: v2(3505.72,3915.7) 3507.58,3917.55 3520.98,3917.55 3579.73,3976.29 3613.24,3976.29 U7.114@3738.47,4101.53 4156.94,4520 U2.1@4440,4520 4530.93,4520 4605.53,4445.4 4905.4,4445.4 4980,4520 U1.1@5006.38,4520
  Bottom Layer w10: Con1.53@3048.42,5117.22 3092.95,5161.75 3566.87,5161.75 3592.95,5135.66 3592.95,4898.77 3306.21,4612.03 3306.21,4603.29 3247.76,4544.84 3219.98,4544.84 3199.7,4524.56 3199.7,4503.15 3199.68,4392.35 3179.68,4372.35 3179.68,4231.82 3345.46,4066.05 3355.38,4066.05 v2(3505.72,3915.7)
NetCon1_54: Con1.54 U1.7 U2.7 U7.102 | length 3682.9
  Top Layer w10: v2(3482.47,3544.22) 3484.32,3546.07 3484.32,3552.92 3601.56,3670.16 3613,3670.16 3677.68,3734.84 3806.23,3734.84 U7.102@3955.69,3884.31 4291.38,4220 4490,4220 4564.6,4145.4 4900.62,4145.4 4940.62,4185.4 4943.69,4185.4 4978.28,4220 U1.7@5006.38,4220
  Bottom Layer w10: Con1.54@2948.42,5117.22 3092.95,4972.69 3092.95,4671.24 3070,4648.28 3070,4218.92 3465.3,3823.62 3465.3,3564.01 3482.47,3546.84 v2(3482.47,3544.22)
NetCon1_55: Con1.55 U2.26 U7.113 | length 3255.4
  Top Layer w10: v2(3420.86,3814.27) 3497.44,3890.86 3522.57,3890.86 3588.01,3956.29 3629.44,3956.29 U7.113@3756.57,4083.43 4167.99,4494.84 4514.22,4494.84 4539.06,4470 4552.65,4470 4602.65,4420 U2.26@4813.62,4420
  Bottom Layer w10: Con1.55@2848.42,5117.22 3003.9,4961.75 3003.9,4586.39 3030,4560.29 3030,4188.65 3404.23,3814.42 3420.71,3814.42 v2(3420.86,3814.27)
NetCon1_56: Con1.56 U1.6 U2.6 U7.103 | length 3767.4
  Top Layer w10: v2(3446.92,3536.95) 3446.92,3539.57 3457.63,3550.28 3457.63,3554.51 3582.29,3679.17 3582.29,3684.3 3588.15,3690.16 3604.71,3690.16 3669.4,3754.84 3790.02,3754.84 U7.103@3937.59,3902.41 ; U7.103@3960.4,3929.6 4300.8,4270 4510,4270 4584.6,4195.4 4870.27,4195.4 4900.27,4225.4 4915.4,4225.4 4957.09,4267.09 5003.47,4267.09 U1.6@5006.38,4270
  Bottom Layer w10: Con1.56@2748.42,5117.22 2903.9,4961.75 2903.9,4272.69 3445.3,3731.29 3445.3,3538.58 v2(3446.92,3536.95)
NetCon1_57: Con1.57 U1.2 U2.2 U7.112 | length 3902.7
  Top Layer w10: v2(3330.72,3684.15) 3332.57,3686 3332.57,3697.7 3424.3,3789.43 3431.15,3789.43 3512.57,3870.86 3530.86,3870.86 3594.84,3934.84 3644.19,3934.84 U7.112@3774.67,4065.33 4184.19,4474.84 4293.76,4474.84 4298.6,4470 4510.78,4470 4532.7,4448.08 4545.05,4448.08 4597.74,4395.4 4870.27,4395.4 4900.27,4425.4 4913.69,4425.4 4958.28,4470 U1.2@5006.38,4470
  Bottom Layer w10: Con1.57@2648.42,5117.22 2703.9,5061.75 2703.9,4550.68 2731.36,4523.22 2731.36,4090.36 3137.57,3684.15 v2(3330.72,3684.15)
NetCon1_58: Con1.58 U1.5 U2.5 U7.104 | length 4082.8
  Top Layer w10: v2(3394.99,3495.01) 3422.08,3522.1 3422.08,3547.24 3504.84,3630 3504.84,3635.14 3579.86,3710.16 3596.43,3710.16 3661.11,3774.84 3773.82,3774.84 U7.104@3919.49,3920.51 4314.14,4315.16 4360.29,4315.16 4365.13,4320 4490,4320 4560,4250 4720.29,4250 4724.89,4245.4 4895.4,4245.4 4937.09,4287.09 4977.01,4287.09 5006.38,4316.46 U1.5@5006.38,4320
  Bottom Layer w10: Con1.58@2548.42,5117.22 2603.9,5061.75 2603.9,4639.12 2640.76,4602.26 2640.76,4570.95 2663.9,4547.81 2663.9,4534.11 2691.36,4506.65 2691.36,4073.79 3145.15,3620 3164.6,3620 3167.09,3622.49 3187.67,3622.49 3190.16,3620 3200,3620 3324.99,3495.01 v2(3394.99,3495.01)
NetCon1_59: Con1.59 U1.23 U2.23 U7.110 | length 4610.9
  Top Layer w10: v2(3217.43,3567.43) 3309.31,3659.31 3364.44,3659.31 3384.84,3679.71 3384.84,3684.84 3530.16,3830.16 3546.73,3830.16 3611.41,3894.84 3676.6,3894.84 U7.110@3810.88,4029.12 3997.86,4216.1 3997.86,4222.99 4154.87,4380 v2(4190,4380) ; v2(4350,4340) 4352.62,4340 4357.22,4344.6 4496.65,4344.6 4511.06,4330.19 4511.06,4328.94 4570,4270 U2.23@4813.62,4270 4891.72,4270 4929.02,4307.3 4937,4307.3 4974.3,4344.6 5122.48,4344.6 5197.08,4270 U1.23@5380,4270
  Bottom Layer w10: Con1.59@2448.42,5117.22 2570,4995.65 2570,4967.6 2564.14,4961.75 2529.98,4961.75 2503.9,4935.66 2503.9,4898.77 2581.52,4821.15 2581.52,4591.23 2591.07,4581.68 2591.07,4550.36 2651.36,4490.08 2651.36,4048.64 3130,3570 3175.75,3570 3178.32,3567.43 v2(3217.43,3567.43) ; v2(4190,4380) 4310,4380 v2(4350,4340)
NetCon1_60: Con1.60 U1.4 U2.4 U7.105 | length 4801
  Top Layer w10: v2(3300,3420) 3370.15,3490.15 3370.15,3505.3 3390.77,3525.92 3390.77,3544.21 3484.84,3638.29 3484.84,3643.42 3571.58,3730.16 3588.15,3730.16 3652.83,3794.84 3757.61,3794.84 U7.105@3901.39,3938.61 4332.77,4370 U2.4@4440,4370 4441.92,4368.08 4511.92,4368.08 4584.6,4295.4 4883.4,4295.4 4920.7,4332.7 4934.12,4332.7 4971.42,4370 U1.4@5006.38,4370
  Bottom Layer w10: Con1.60@2348.42,5117.22 2295.64,5170 2120,5170 2100,5150 2100,4890 2200,4790 2200,4771.73 2531.36,4440.37 2531.36,3998.94 3110.29,3420 v2(3300,3420)
NetCon1_61: Con1.61 U1.21 U2.21 U7.109 | length 4683.9
  Top Layer w10: v2(3240,3490) 3240,3525.13 3326.08,3611.21 3344.63,3611.21 3404.84,3671.43 3404.84,3676.56 3538.44,3810.16 3555.01,3810.16 3619.69,3874.84 3692.8,3874.84 U7.109@3828.98,4011.02 3828.98,4012.13 4058.15,4241.3 4058.15,4248.15 v2(4060,4250) ; v2(4325.23,4245) 4495,4245 4495.4,4244.6 4496.65,4244.6 4511.06,4230.19 4511.06,4228.94 4570,4170 U2.21@4813.62,4170 4816.53,4172.91 4876.06,4172.91 4908.55,4205.4 4935.4,4205.4 4974.6,4244.6 5138.26,4244.6 5212.86,4170 U1.21@5380,4170
  Bottom Layer w10: Con1.61@2248.42,5117.22 2303.9,5061.75 2303.9,4774.39 2328.42,4749.86 2328.42,4728.16 2591.36,4465.22 2591.36,4023.79 3125.15,3490 v2(3240,3490) ; v2(4060,4250) 4295.39,4250 4300.39,4245 v2(4325.23,4245)
NetCon1_62: Con1.62 U1.3 U2.3 U7.106 | length 4460.2
  Top Layer w10: v2(3313.16,3473.16) 3350.15,3510.15 3350.15,3513.58 3370.77,3534.2 3370.77,3552.5 3464.84,3646.57 3464.84,3651.7 3563.3,3750.16 3579.86,3750.16 3644.55,3814.84 3741.41,3814.84 U7.106@3883.29,3956.71 4129.21,4202.64 4129.21,4219.5 4329.71,4420 U2.3@4440,4420 4442.91,4417.09 4507.12,4417.09 4516.13,4408.08 4528.48,4408.08 4591.17,4345.4 4876.84,4345.4 4914.14,4382.7 4927.55,4382.7 4964.85,4420 U1.3@5006.38,4420
  Bottom Layer w10: Con1.62@2148.42,5117.22 2200,5065.64 2200,4818.28 2288.42,4729.86 2288.42,4711.59 2551.36,4448.66 2551.36,4007.22 3118.58,3440 3280,3440 v2(3313.16,3473.16)
NetCON2_5: CON2.5 J5.20 R30.2 | length 2742.6
  Top Layer w20: R30.2@5981.1,6910 5981.1,6981.1 6025,7025 J5.20@6025,7274.8
  Bottom Layer w20: CON2.5@3855,7303.82 3943.68,7392.5 3943.68,7404.15 4049.53,7510 5789.8,7510 J5.20@6025,7274.8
